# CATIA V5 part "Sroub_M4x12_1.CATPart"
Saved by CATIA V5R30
Part number: Sroub_M4x12_1
Nomenclature: E1200/4x12
Description: MEUSBURGER
Publications: "DrillHole", "TapHole", "Base"
Bounding box of the stored display mesh (mm): x -3.499 to 3.499, y -3.495 to 3.495, z -4 to 12
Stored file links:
  E:\Bakalarka\Model\Forma_v7\Sroub_M4x12_1.CATPart
  E:\dev\MoldDesign\intel_a\startup\components\MoldCatalog\CapScrew\Meusburger\CapScrew_E1200\TableE1200.txt
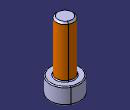
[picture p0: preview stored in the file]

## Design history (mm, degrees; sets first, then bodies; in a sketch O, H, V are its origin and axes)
Parameters
  Ref = "E1200/4x12" {design table}
  L = 12 mm {design table}
  D = 4 mm {design table}
  D1 = 4 mm {design table}
  D3 = 7 mm {design table}
  L1 = 12 mm {design table}
  L2 = 12 mm {design table}
  L3 = 4 mm {design table}
  SW = 3 mm {design table}
  dkren = 3.14 mm {design table}
  L4 = 2 mm {design table}
  R = 0.2 mm {design table}
  R1 = 0.4 mm {design table}
  F = 0.4 mm {design table}
  kdkern = 3.24 mm {design table}
  kd1 = 4.5 mm {design table}
  kl1 = 10 mm {design table}
  kd3 = 8 mm {design table}
  kl3 = 4.5 mm {design table}
  kl = 20.5 mm {design table}
  c = 4 mm {design table}
  ThreadString = "M4" {design table}
  Mat = "" {design table}
  HeatTreat = "" {design table}
  SupplierRef = "Meusburger 2017"
  BmpRef = "F_MldCapScrewLD"
  DrillHole_Length = 225 mm
  HeadThick = 4 mm {= L3}
  HeadDiam = 7 mm {= D3}
  ScrewThread = 12 mm {= Thread1.Depth}
  ScrewPitch = 0.7 mm {= Thread1.Pitch}
Set1 "BaseBody"
  Point1 "Base": (0, 0, 0)
  Plane1: type Offset, RefPlane xy-plane, Offset 225 {= DrillHole_Length}, reversed
Body1 "PartBody" (main body)
  Sketch1 on yz-plane, origin (0, 0, 0), H (0, 0, -1), V (0, 1, 0)
    point P1 (4, 0)
    line L1 (4, 0) -> (4, -3.5)
    line L2 (4, -3.5) -> (0, -3.5)
    line L3 (0, -3.5) -> (0, -2)
    point P5 (0, -2)
    line L4 (0, -2) -> (-12, -2)
    line L5 (-12, -2) -> (-12, 0)
    point P7 (-12, 0)
    axis line L6 (-12, 0) -> (4, 0)
    point P8 (4, 0)
    construction line L7 (0, -2) -> (0, -2)
    line L8 (0, 0) -> (-12, 0)
    point P9 (-12, -2)
    point P10 (-12, -2)
    line L9 (0, 0) -> (4, 0)
    length L1 = 3.5 {= D3 /2}
    distance L1 L3 = 4 {= L3}
    distance L4 L6 = 2 {= D /2}
    distance L3 L5 = 12 {= L}
    distance L5 P5 = 12 {= L1}
    coincidence: P1 L6, L6 H, P8 L1, P9 P10, P7 L5, L3 V
    vertical: L1 V, L3 V, L5 V
    horizontal: L2 H, L4 H, L7 H, L8 H, L9 H
  Shaft1: profile Sketch1, axis Sketch1.L6, angle 360
  Sketch2 on face of Shaft1 from Sketch1.L1, origin (0, 0, -4), H (1, 0, 0), V (0, -1, 0)
    point P1 (-0.866, -1.5)
    point P2 (0.866, -1.5)
    point P3 (1.7321, 0)
    point P4 (0.866, 1.5)
    point P5 (-0.866, 1.5)
    point P6 (-1.7321, 0)
    point P7 (0, -1.5)
    line L1 (-0.866, -1.5) -> (0.866, -1.5)
    line L2 (0.866, -1.5) -> (1.7321, 0)
    line L3 (1.7321, 0) -> (0.866, 1.5)
    line L4 (0.866, 1.5) -> (-0.866, 1.5)
    line L5 (-0.866, 1.5) -> (-1.7321, 0)
    line L6 (-1.7321, 0) -> (-0.866, -1.5)
    construction line L7 (0, 0) -> (0, -1.5)
    construction circle A1 centre (0, 0) radius 1.7321
    construction arc A2 centre (-0.866, 1.5) radius 1.7321 from (0.866, 1.5) to (-1.7321, 0) cw
    construction arc A3 centre (0.866, -1.5) radius 1.7321 from (1.7321, 0) to (-0.866, -1.5) ccw
    point P8 (-0.866, 1.5)
    point P9 (0.866, -1.5)
    distance L1 L4 = 3 {= SW}
    coincidence: A1 P1, A1 P2, A1 P3, A1 P4, A1 P5, A1 P6, A2 P4, A2 P6, A2 O, P8 P5, A3 P3, A3 P1, A3 O, P9 P2, P3 H
    midpoint: P7 L1
  Pocket1: profile Sketch2, direction (0, 0, 1), length 2 {= L4}
  Thread1: "M4", diameter 4, depth 12 {= L2}, pitch 0.7, on face of Shaft1 from Sketch1.L4, from face of Shaft1 from Sketch1.L5
  Fillet1: radius 0.4 {= R1}, on edge [face of Shaft1 from Sketch1.L2 | face of Shaft1 from Sketch1.L1]
  Fillet2: radius 0.2 {= R}, on edge [face of Shaft1 from Sketch1.L3 | face of Shaft1 from Sketch1.L2]
  Fillet3: radius 0.2 {= R}, on edge [face of Shaft1 from Sketch1.L4 | face of Shaft1 from Sketch1.L3]
  Chamfer1: length 0.4 {= F}, angle 45, on edge [face of Shaft1 from Sketch1.L5 | face of Shaft1 from Sketch1.L4]
Body2 "DrillHole"
  Sketch3 on Plane1, origin (22.3066, -22.3066, -225), H (1, 0, 0), V (0, 1, 0)
    point P1 (-22.3066, 22.3066)
    reference projected circle E1 centre (-22.3066, 22.3066) radius 3.5 from edge [face of Shaft1 from Sketch1.L3 | face of Shaft1 from Sketch1.L2]
    concentricity: E1 P1
  Hole1: placed by Sketch3, at (0, 0, -225) direction (0, 0, 1), diameter 4.5 {= kd1}, depth 237 {= DrillHole_Length +L1}, counterbore diameter 8 {= kd3}, counterbore depth 225 {= DrillHole_Length}
Body3 "TapHole"
  Sketch4 on Plane1, origin (0, 0, -225), H (1, 0, 0), V (0, 1, 0)
    point P1 (0, 0)
    reference projected point E1 (0, 0) from Point1
    coincidence: E1 P1
  Hole2: placed by Sketch4, at (0, 0, -225) direction (0, 0, 1), diameter 3.242, depth 245.5 {= DrillHole_Length +kl}, V-bottom angle 120, threaded "M4", thread diameter 4, thread depth 245.5 {= DrillHole_Length +kl}, pitch 0.7
Relations
  design table "TableE1200", configuration 22, drives Ref, L, D, D1, D3, L1, L2, L3, SW, dkren, L4, R, R1, F, kdkern, kd1, kl1, kd3, kl3, kl, c, ThreadString, Mat, HeatTreat
  Thread1.ThreadDescription = ThreadString
  Hole2.ThreadDescription = ThreadString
